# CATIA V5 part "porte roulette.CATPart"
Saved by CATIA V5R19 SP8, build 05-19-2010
Part number: porte roulettes d
Bounding box of the stored display mesh (mm): x 0 to 12.5, y -14.496 to 16, z -10 to 5
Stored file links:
  G:\EU_thinkMotion\CFAO_2010\MMS_groupe3\MMS_groupe3\A reprendre\ftixier\florent-tixier\florent-tixier\porte roulette.CATPart
  C:\Users\Azote\Desktop\CFAO\coupe_tube1.CATProduct
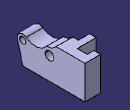
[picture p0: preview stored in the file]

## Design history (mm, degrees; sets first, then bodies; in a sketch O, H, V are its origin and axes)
External parameters (linked from other documents)
  External.e = 12 mm
  External.R11 = 5 mm
  `External.rayon_axe_roulette coupe` = 1.5 mm
  External.rayon_axe_rouleau = 2 mm
  External.diametre_gorge_vis = 4 mm
  External.diametre_tete_vis = 5 mm
  External.profondeur_lamage = 2 mm
  External.prodondeur_trou = 10 mm
Set1
  Point1 "centre_roulette_coupe": linked copy from another document
  Line1 "Axe_vis": linked copy from another document
  Line2 "suport_axe_rouleau": linked copy from another document
  Point2 "centre_rouleau": linked copy from another document
  Point3 "Centre_roulette_chanfreinage": linked copy from another document
Body1 (main body)
  Sketch1 on yz-plane, origin (0, 0, 0), H (0, 1, 0), V (0, 0, 1)
    line L1 (16, -10) -> (-12, -10)
    line L2 (-12, -10) -> (-14.4959, -0.1425)
    point P3 (-14.4959, -0.1425)
    point P4 (-14.4959, -0.1425)
    arc A1 centre (-12, 0) radius 2.5 from (-14.4959, -0.1425) to (-10.3925, 1.9147) cw
    line L3 (16, -10) -> (16, 5)
    line L4 (16, 5) -> (3, 5)
    reference projected point E1 (-12, 0) from Point1
    arc A2 centre (-6.3469, 6.7333) radius 6.2917 from (-10.3925, 1.9147) to (-1.2388, 3.06) ccw
    arc A3 centre (-0.7939, 7.6887) radius 4.6501 from (-1.2388, 3.06) to (3, 5) ccw
    point P11 (-1.2388, 3.06)
    reference projected line E2 (-6, -42.6969) -> (-6, 52.3031) from Line1
    reference projected line E3 (14, 0) -> (-26, 0) from Line2
    reference projected line E4 (14, 0) -> (-26, 0) from Line2
    circle A4 centre (0, 0) radius 2
    circle A5 centre (-12, 0) radius 1.5
    reference projected point E5 (0, 0) from Point2
    reference projected point E6 (-12, 0) from Point1
    length L1 = 28 {= External.e +16mm}
    radius A1 = 2.5
    length L4 = 13
    distance L3 E2 = 22
    distance E3 L4 = 5 {= External.R11}
    distance L1 E4 = 10
    radius A5 = 1.5 {= `External.rayon_axe_roulette coupe`}
    radius A4 = 2 {= External.rayon_axe_rouleau}
    horizontal: L1 H, L4 H
    vertical: L3 V
    concentricity: E1 A1, A4 E5, A5 E6
    coincidence: P4 P3, A3 P11, P11 A2
    tangency: A2 A1
  Pad1: profile Sketch1, direction (1, 0, 0), length 12.5
  Sketch2 on xy-plane, origin (0, 0, 0), H (1, 0, 0), V (0, 1, 0)
    point P1 (0, 5.5)
    line L1 (0, 5.5) -> (5, 5.5)
    line L2 (5, 5.5) -> (5, -24.5)
    line L3 (5, -24.5) -> (0, -24.5)
    line L4 (0, -24.5) -> (0, 5.5)
    reference projected line E1 (0, 16) -> (4, 16) from edge [face of Pad1 from Sketch1.L4 | face of Pad1 from Sketch1.L3]
    length L1 = 5
    length L2 = 30
    distance L1 E1 = 10.5
    coincidence: P1 V
    horizontal: L1 H, L3 H
    vertical: L2 V, L4 V
  Pocket1: profile Sketch2, direction (0, 0, -1), length 5.5 {= External.R11 +0.5mm}, opposite side length 5 {= External.R11}
  Sketch3 on end face of Pocket1, origin (1.4152, -5.7216, -5.5), H (1, 0, 0), V (0, 1, 0)
    point P1 (-1.4152, -0.2784)
    reference projected point E1 (-1.4152, -0.2784) from Point3
    coincidence: P1 E1
  Hole1: placed by Sketch3, at (0, -6, -5.5) direction (0, 0, -1), diameter 4 {= External.diametre_gorge_vis}, through (limit type 6), counterbore diameter 6 {= External.diametre_tete_vis +1mm}, counterbore depth 2 {= External.profondeur_lamage}
  Sketch4 on face of Pad1 from Sketch1.L4, origin (0, 0, 5), H (1, 0, 0), V (0, 1, 0)
    point P1 (0, 16)
    line L1 (0, 16) -> (5.5, 16)
    line L2 (5.5, 16) -> (5.5, 13)
    line L3 (5.5, 13) -> (8.5, 13)
    line L4 (8.5, 13) -> (8.5, 8.5)
    line L5 (8.5, 8.5) -> (0, 8.5)
    point P6 (0, 8.5)
    line L6 (0, 8.5) -> (0, 16)
    reference projected line E1 (0, 16) -> (12.5, 16) from edge [face of Pad1 from Sketch1.L4 | face of Pad1 from Sketch1.L3]
    length L5 = 8.5
    length L4 = 4.5
    length L2 = 3
    distance L4 L2 = 3
    coincidence: P1 V, P6 V, E1 L1
    horizontal: L1 H, L3 H, L5 H
    vertical: L2 V, L4 V, L6 V
  Pocket2: profile Sketch4, direction (0, 0, -1), through (limit type 6)
Relations
  Hole1.Depth = External.prodondeur_trou (deactivated)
